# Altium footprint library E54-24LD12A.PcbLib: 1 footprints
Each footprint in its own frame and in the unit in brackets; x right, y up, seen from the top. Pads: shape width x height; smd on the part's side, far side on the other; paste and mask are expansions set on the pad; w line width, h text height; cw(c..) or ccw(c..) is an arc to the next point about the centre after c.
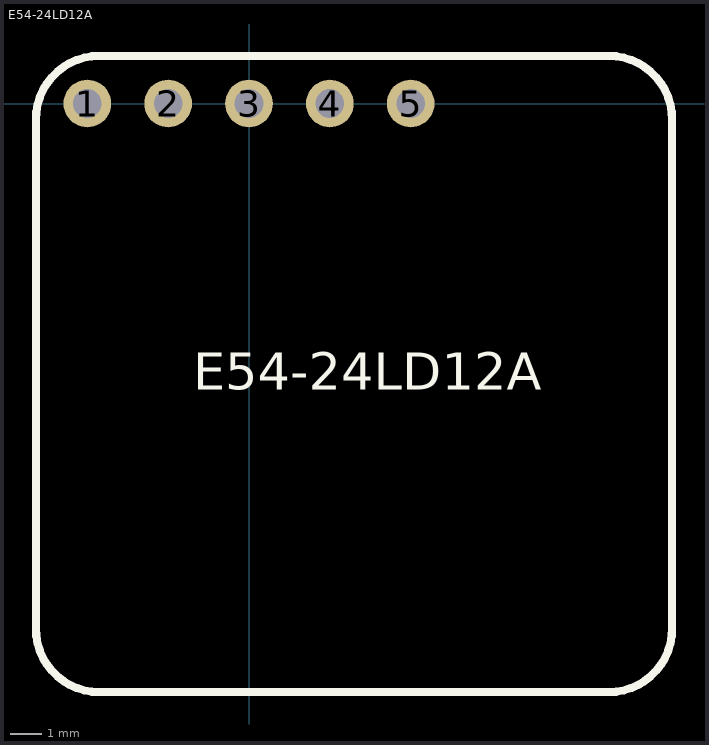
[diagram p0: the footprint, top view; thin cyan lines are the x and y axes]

## E54-24LD12A [mm]
pads (5):
  round 1.5 hole 0.9 paste-2539.97 mask+0: 1(-5.08,0) 2(-2.54,0) 3(0,0) 4(2.54,0) 5(5.08,0)
Top Overlay:
  lines w0.254: -6.7,-16.5 ccw(c-4.7,-16.5) -4.7,-18.5 11.3,-18.5 ccw(c11.3,-16.5) 13.3,-16.5 13.3,-0.5 ccw(c11.3,-0.5) 11.3,1.5 -4.7,1.5 ccw(c-4.7,-0.5) -6.7,-0.5 -6.7,-16.5
  text "E54-24LD12A" at -1.746,-9.395 h2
